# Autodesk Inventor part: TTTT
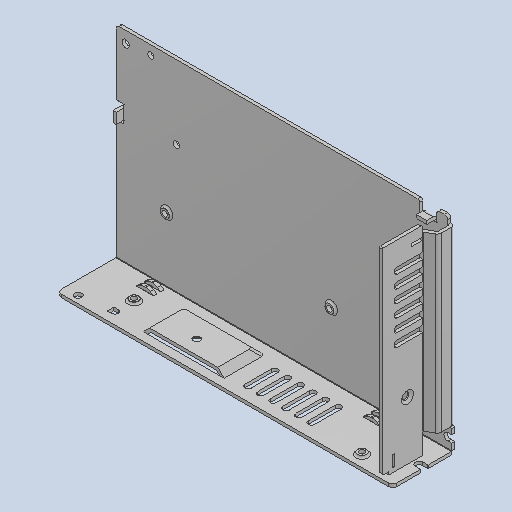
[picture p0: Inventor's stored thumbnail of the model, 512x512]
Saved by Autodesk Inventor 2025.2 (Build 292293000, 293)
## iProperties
Created: 2025-04
Part Number: TTTT
Material: Generic
Description: NOT SPECIFIED
Document SubType Name: Modeling
Designer: BennF
Density: 1 g/cm^3
Appearance: Default
Author: BennF
Revision Number: 4LAST_VERSION
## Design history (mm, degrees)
feature "Base1"
body "Solid1"
